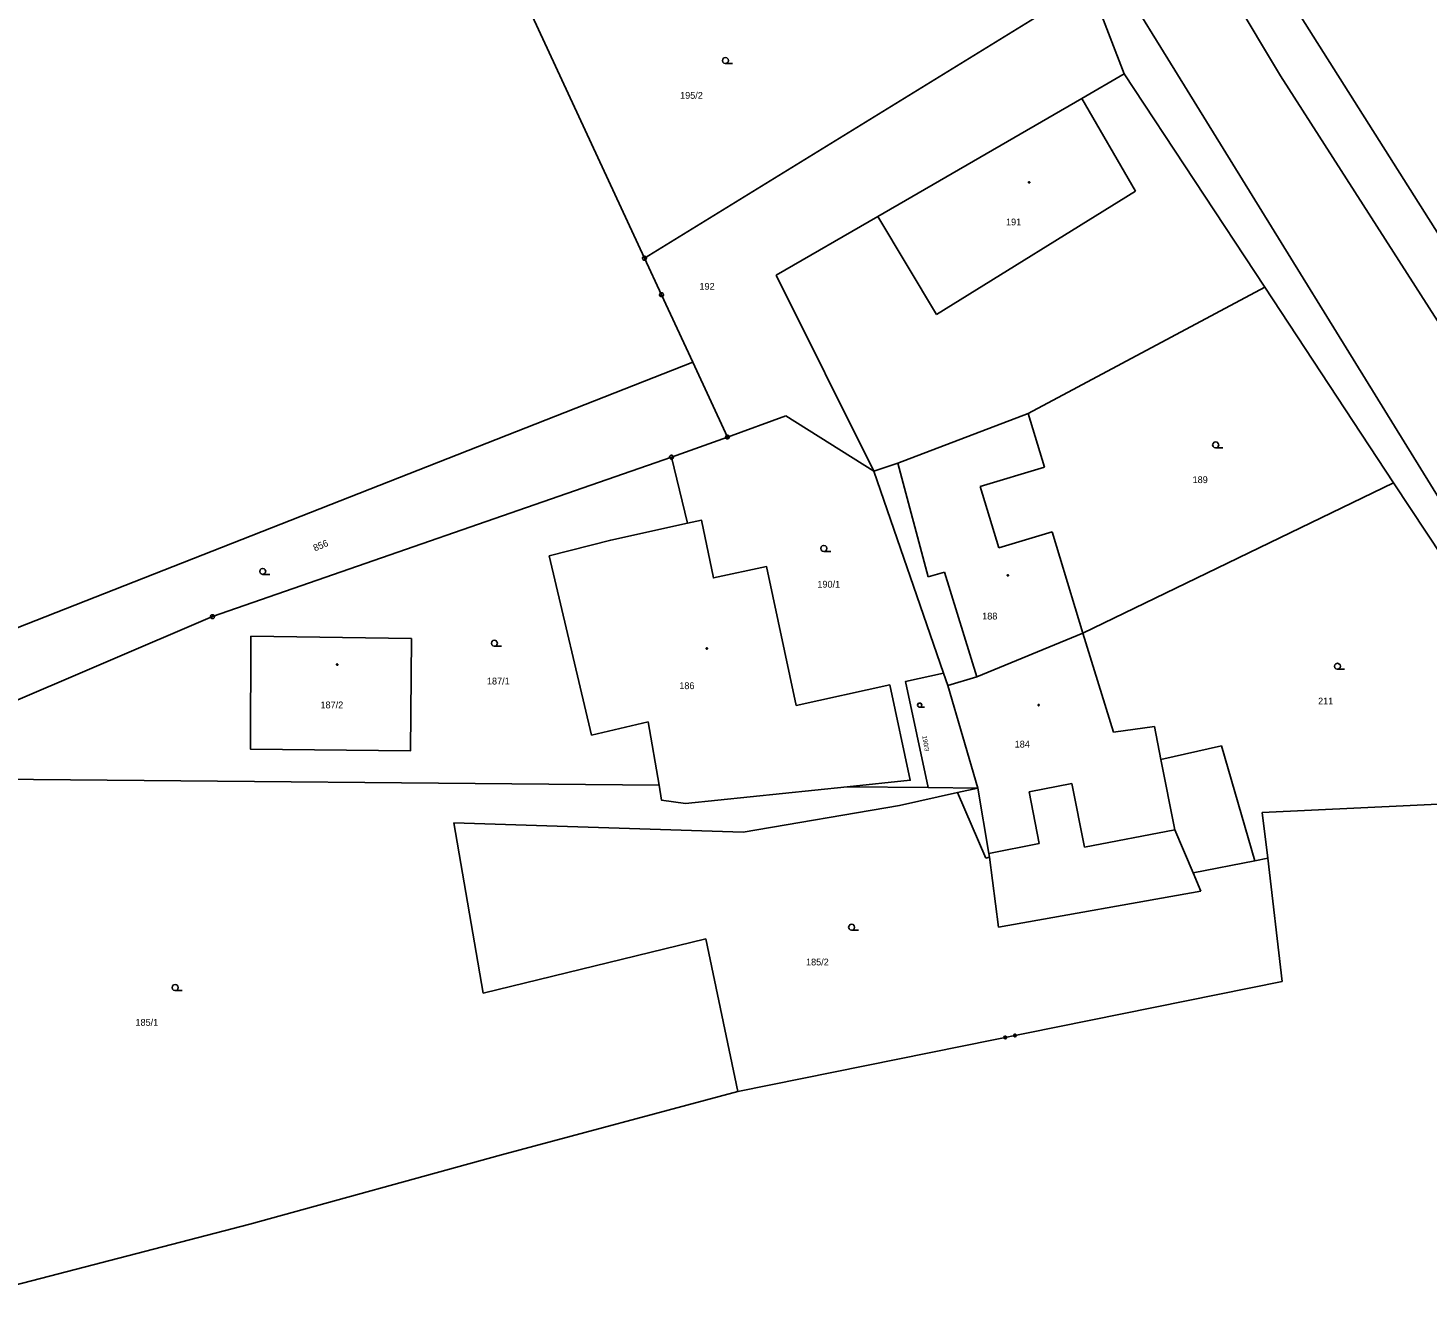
# Model space of a CAD drawing. Extents: x -871430 to -870620, y -1010094 to -1009649.
# Drawn here: x -870992.6 to -870905.1, y -1010094.1 to -1010013.9 of the extents above; entities that cross this region are included whole.
import ezdxf

# ---------------------------------------------------------------- set-up
doc = ezdxf.new("R2010")
doc.units = 0
for name, color, linetype in [('Vrstva 1', 7, 'Continuous'), ('Vrstva 2', 7, 'Continuous'), ('Vrstva 3', 7, 'Continuous'), ('Vrstva 4', 7, 'Continuous'), ('Vrstva 5', 7, 'Continuous'), ('Vrstva 8', 7, 'Continuous')]:
    doc.layers.add(name, color=color, linetype=linetype)

msp = doc.modelspace()

# ---------------------------------------------------------------- linework, layer by layer
at = {"layer": 'Vrstva 1'}
for p, q in [((-870900.92, -1010032.45), (-870917.34, -1010006.41)), ((-870926.27, -1010011.19), (-870954.09, -1010028.31)), ((-870924.1, -1010016.79), (-870926.27, -1010011.19)), ((-870954.09, -1010028.31), (-870961.11, -1010013.17)), ((-870924.1, -1010016.79), (-870926.76, -1010018.33)), ((-870915.32, -1010030.12), (-870924.1, -1010016.79)), ((-870939.51, -1010025.71), (-870926.76, -1010018.33)), ((-870945.85, -1010029.37), (-870939.51, -1010025.71)), ((-870953.03, -1010030.59), (-870954.09, -1010028.31)), ((-870945.85, -1010029.37), (-870939.76, -1010041.62)), ((-870953.03, -1010030.59), (-870951.07, -1010034.81)), ((-870930.1, -1010038.02), (-870915.32, -1010030.12)), ((-870907.27, -1010042.34), (-870915.32, -1010030.12)), ((-871000.46, -1010054.22), (-870951.07, -1010034.81)), ((-870951.07, -1010034.81), (-870948.91, -1010039.48)), ((-870945.25, -1010038.16), (-870948.91, -1010039.48)), ((-870939.76, -1010041.62), (-870945.25, -1010038.16)), ((-870938.26, -1010041.12), (-870930.1, -1010038.02)), ((-870930.1, -1010038.02), (-870929.09, -1010041.37)), ((-870948.91, -1010039.48), (-870952.4, -1010040.74)), ((-870952.4, -1010040.74), (-870981.09, -1010050.7)), ((-870951.39, -1010044.87), (-870952.4, -1010040.74)), ((-870938.26, -1010041.12), (-870939.76, -1010041.62)), ((-870929.09, -1010041.37), (-870933.11, -1010042.58)), ((-870939.76, -1010041.62), (-870935.39, -1010054.23)), ((-870933.11, -1010042.58), (-870931.95, -1010046.41)), ((-870926.69, -1010051.73), (-870907.27, -1010042.34)), ((-870894.37, -1010061.92), (-870907.27, -1010042.34)), ((-870928.61, -1010045.4), (-870931.95, -1010046.41)), ((-870928.61, -1010045.4), (-870926.69, -1010051.73)), ((-870981.09, -1010050.7), (-871004.66, -1010060.76)), ((-870933.31, -1010054.47), (-870926.69, -1010051.73)), ((-870926.69, -1010051.73), (-870924.77, -1010057.92)), ((-870935.39, -1010054.23), (-870935.12, -1010055.01)), ((-870933.31, -1010054.47), (-870935.12, -1010055.01)), ((-870935.12, -1010055.01), (-870933.26, -1010061.41)), ((-870924.77, -1010057.92), (-870922.21, -1010057.57)), ((-870921.82, -1010059.62), (-870922.21, -1010057.57)), ((-870921.82, -1010059.62), (-870918.03, -1010058.77)), ((-870918.03, -1010058.77), (-870915.95, -1010065.95)), ((-871004.66, -1010060.76), (-870953.18, -1010061.23)), ((-870941.43, -1010061.33), (-870936.36, -1010061.38)), ((-870936.36, -1010061.38), (-870933.26, -1010061.41)), ((-870934.53, -1010061.69), (-870933.26, -1010061.41)), ((-870938.15, -1010062.49), (-870934.53, -1010061.69)), ((-870932.75, -1010065.79), (-870934.53, -1010061.69)), ((-870915.49, -1010062.94), (-870894.37, -1010061.92)), ((-870947.92, -1010064.16), (-870938.15, -1010062.49)), ((-870915.13, -1010065.79), (-870915.49, -1010062.94)), ((-870964.17, -1010074.23), (-870966, -1010063.59)), ((-870966, -1010063.59), (-870947.92, -1010064.16)), ((-870932.75, -1010065.79), (-870932.53, -1010065.73)), ((-870932.53, -1010065.73), (-870931.97, -1010070.11)), ((-870915.13, -1010065.79), (-870915.95, -1010065.95)), ((-870914.23, -1010073.5), (-870915.13, -1010065.79)), ((-870915.95, -1010065.95), (-870919.79, -1010066.7)), ((-870919.31, -1010067.86), (-870919.79, -1010066.7)), ((-870931.97, -1010070.11), (-870919.31, -1010067.86)), ((-870950.25, -1010070.83), (-870964.17, -1010074.23)), ((-870948.25, -1010080.36), (-870950.25, -1010070.83)), ((-870948.25, -1010080.36), (-870914.23, -1010073.5)), ((-870963.03, -1010084.32), (-870948.25, -1010080.36)), ((-870978.75, -1010088.66), (-870963.03, -1010084.32)), ((-870999.93, -1010094.14), (-870978.75, -1010088.66))]:
    msp.add_line(p, q, dxfattribs=at)
for points in [[(-870960.05, -1010046.91), (-870956.2, -1010045.92), (-870951.39, -1010044.87)], [(-870951.39, -1010044.87), (-870950.52, -1010044.68), (-870949.78, -1010048.28), (-870946.46, -1010047.57), (-870944.6, -1010056.25), (-870938.76, -1010054.97), (-870937.48, -1010060.92), (-870941.43, -1010061.33)], [(-870953.18, -1010061.23), (-870953.86, -1010057.28), (-870957.39, -1010058.1), (-870960.05, -1010046.91)], [(-870978.7, -1010051.93), (-870968.65, -1010052.07), (-870968.71, -1010059.08), (-870978.71, -1010058.99), (-870978.7, -1010051.93)], [(-870936.36, -1010061.38), (-870937.78, -1010054.76), (-870935.39, -1010054.23)], [(-870953.18, -1010061.23), (-870953.02, -1010062.17), (-870951.53, -1010062.38), (-870941.43, -1010061.33)], [(-870931.518, -1010076.904), (-870931.462, -1010076.942), (-870931.449, -1010077.008), (-870931.486, -1010077.064), (-870931.552, -1010077.077), (-870931.608, -1010077.04), (-870931.621, -1010076.974), (-870931.584, -1010076.918), (-870931.518, -1010076.904), (-870931.519, -1010076.915), (-870931.577, -1010076.927), (-870931.593, -1010076.95), (-870931.495, -1010076.93), (-870931.471, -1010076.946), (-870931.609, -1010076.974), (-870931.605, -1010076.993), (-870931.467, -1010076.966), (-870931.463, -1010076.985), (-870931.601, -1010077.013), (-870931.597, -1010077.033), (-870931.46, -1010077.005), (-870931.475, -1010077.028), (-870931.573, -1010077.048), (-870931.55, -1010077.064), (-870931.491, -1010077.052)], [(-870930.905, -1010076.781), (-870930.849, -1010076.818), (-870930.836, -1010076.884), (-870930.873, -1010076.94), (-870930.939, -1010076.954), (-870930.995, -1010076.916), (-870931.009, -1010076.85), (-870930.972, -1010076.794), (-870930.905, -1010076.781), (-870930.911, -1010076.792), (-870930.97, -1010076.804), (-870930.985, -1010076.828), (-870930.887, -1010076.808), (-870930.864, -1010076.823), (-870931.001, -1010076.851), (-870930.997, -1010076.871), (-870930.86, -1010076.843), (-870930.856, -1010076.863), (-870930.993, -1010076.89), (-870930.989, -1010076.91), (-870930.852, -1010076.882), (-870930.867, -1010076.906), (-870930.965, -1010076.926), (-870930.942, -1010076.941), (-870930.883, -1010076.929)]]:
    msp.add_lwpolyline(points, dxfattribs=at)
at = {"layer": 'Vrstva 3'}
for points in [[(-870949.03, -1010016.15), (-870949.125, -1010016.125), (-870949.192, -1010016.055), (-870949.218, -1010015.962), (-870949.192, -1010015.87), (-870949.125, -1010015.8), (-870949.03, -1010015.775), (-870948.935, -1010015.8), (-870948.868, -1010015.87), (-870948.842, -1010015.962), (-870948.868, -1010016.055), (-870948.935, -1010016.125), (-870949.03, -1010016.15), (-870948.592, -1010016.15)], [(-870918.39, -1010040.16), (-870918.485, -1010040.135), (-870918.552, -1010040.065), (-870918.578, -1010039.972), (-870918.552, -1010039.88), (-870918.485, -1010039.81), (-870918.39, -1010039.785), (-870918.295, -1010039.81), (-870918.228, -1010039.88), (-870918.202, -1010039.972), (-870918.228, -1010040.065), (-870918.295, -1010040.135), (-870918.39, -1010040.16), (-870917.952, -1010040.16)], [(-870942.88, -1010046.63), (-870942.975, -1010046.605), (-870943.042, -1010046.535), (-870943.068, -1010046.442), (-870943.042, -1010046.35), (-870942.975, -1010046.28), (-870942.88, -1010046.255), (-870942.785, -1010046.28), (-870942.718, -1010046.35), (-870942.692, -1010046.442), (-870942.718, -1010046.535), (-870942.785, -1010046.605), (-870942.88, -1010046.63), (-870942.442, -1010046.63)], [(-870977.95, -1010048.06), (-870978.045, -1010048.035), (-870978.112, -1010047.965), (-870978.138, -1010047.872), (-870978.112, -1010047.78), (-870978.045, -1010047.71), (-870977.95, -1010047.685), (-870977.855, -1010047.71), (-870977.788, -1010047.78), (-870977.762, -1010047.872), (-870977.788, -1010047.965), (-870977.855, -1010048.035), (-870977.95, -1010048.06), (-870977.512, -1010048.06)], [(-870963.47, -1010052.55), (-870963.565, -1010052.525), (-870963.632, -1010052.455), (-870963.658, -1010052.362), (-870963.632, -1010052.27), (-870963.565, -1010052.2), (-870963.47, -1010052.175), (-870963.375, -1010052.2), (-870963.308, -1010052.27), (-870963.282, -1010052.362), (-870963.308, -1010052.455), (-870963.375, -1010052.525), (-870963.47, -1010052.55), (-870963.032, -1010052.55)], [(-870910.78, -1010053.99), (-870910.875, -1010053.965), (-870910.942, -1010053.895), (-870910.968, -1010053.802), (-870910.942, -1010053.71), (-870910.875, -1010053.64), (-870910.78, -1010053.615), (-870910.685, -1010053.64), (-870910.618, -1010053.71), (-870910.592, -1010053.802), (-870910.618, -1010053.895), (-870910.685, -1010053.965), (-870910.78, -1010053.99), (-870910.342, -1010053.99)], [(-870936.89, -1010056.35), (-870936.954, -1010056.333), (-870936.999, -1010056.286), (-870937.016, -1010056.224), (-870936.999, -1010056.162), (-870936.954, -1010056.116), (-870936.89, -1010056.099), (-870936.826, -1010056.116), (-870936.781, -1010056.162), (-870936.764, -1010056.224), (-870936.781, -1010056.286), (-870936.826, -1010056.333), (-870936.89, -1010056.35), (-870936.597, -1010056.35)], [(-870941.14, -1010070.29), (-870941.235, -1010070.265), (-870941.302, -1010070.195), (-870941.328, -1010070.102), (-870941.302, -1010070.01), (-870941.235, -1010069.94), (-870941.14, -1010069.915), (-870941.045, -1010069.94), (-870940.978, -1010070.01), (-870940.952, -1010070.102), (-870940.978, -1010070.195), (-870941.045, -1010070.265), (-870941.14, -1010070.29), (-870940.702, -1010070.29)], [(-870983.42, -1010074.06), (-870983.515, -1010074.035), (-870983.582, -1010073.965), (-870983.608, -1010073.872), (-870983.582, -1010073.78), (-870983.515, -1010073.71), (-870983.42, -1010073.685), (-870983.325, -1010073.71), (-870983.258, -1010073.78), (-870983.232, -1010073.872), (-870983.258, -1010073.965), (-870983.325, -1010074.035), (-870983.42, -1010074.06), (-870982.982, -1010074.06)]]:
    msp.add_lwpolyline(points, dxfattribs=at)
at = {"layer": 'Vrstva 4'}
for p, q in [((-870991.3, -1009902.71), (-870921.37, -1010015.86)), ((-870914.33, -1010016.91), (-870955.86, -1009947.84)), ((-870921.37, -1010015.86), (-870879.42, -1010083.87)), ((-870873.64, -1010080.52), (-870914.33, -1010016.91)), ((-870923.41, -1010024.12), (-870926.76, -1010018.33)), ((-870935.84, -1010031.82), (-870923.41, -1010024.12)), ((-870939.51, -1010025.71), (-870935.84, -1010031.82)), ((-870938.26, -1010041.12), (-870936.36, -1010048.21)), ((-870936.36, -1010048.21), (-870935.33, -1010047.93)), ((-870935.33, -1010047.93), (-870933.31, -1010054.47)), ((-870920.95, -1010064.01), (-870921.82, -1010059.62)), ((-870932.56, -1010065.5), (-870933.26, -1010061.41)), ((-870927.38, -1010061.12), (-870930.05, -1010061.65)), ((-870926.59, -1010065.11), (-870927.38, -1010061.12)), ((-870930.05, -1010061.65), (-870929.42, -1010064.88)), ((-870920.95, -1010064.01), (-870926.59, -1010065.11)), ((-870919.79, -1010066.7), (-870920.95, -1010064.01)), ((-870929.42, -1010064.88), (-870932.56, -1010065.5)), ((-870932.56, -1010065.5), (-870932.53, -1010065.73))]:
    msp.add_line(p, q, dxfattribs=at)
at = {"layer": 'Vrstva 5'}
for points in [[(-870930.05, -1010023.528), (-870930.025, -1010023.532), (-870930.013, -1010023.555), (-870930.008, -1010023.57), (-870930.013, -1010023.592), (-870930.033, -1010023.61), (-870930.05, -1010023.612), (-870930.072, -1010023.605), (-870930.088, -1010023.59), (-870930.092, -1010023.57), (-870930.088, -1010023.548), (-870930.068, -1010023.53), (-870930.05, -1010023.528)], [(-870931.38, -1010048.078), (-870931.355, -1010048.082), (-870931.342, -1010048.105), (-870931.338, -1010048.12), (-870931.342, -1010048.142), (-870931.362, -1010048.16), (-870931.38, -1010048.162), (-870931.402, -1010048.155), (-870931.418, -1010048.14), (-870931.422, -1010048.12), (-870931.418, -1010048.098), (-870931.398, -1010048.08), (-870931.38, -1010048.078)], [(-870950.19, -1010052.648), (-870950.165, -1010052.652), (-870950.152, -1010052.675), (-870950.148, -1010052.69), (-870950.152, -1010052.712), (-870950.172, -1010052.73), (-870950.19, -1010052.732), (-870950.212, -1010052.725), (-870950.227, -1010052.71), (-870950.232, -1010052.69), (-870950.227, -1010052.668), (-870950.207, -1010052.65), (-870950.19, -1010052.648)], [(-870973.29, -1010053.658), (-870973.265, -1010053.662), (-870973.253, -1010053.685), (-870973.248, -1010053.7), (-870973.253, -1010053.722), (-870973.273, -1010053.74), (-870973.29, -1010053.742), (-870973.312, -1010053.735), (-870973.328, -1010053.72), (-870973.332, -1010053.7), (-870973.328, -1010053.678), (-870973.308, -1010053.66), (-870973.29, -1010053.658)], [(-870929.45, -1010056.188), (-870929.425, -1010056.192), (-870929.412, -1010056.215), (-870929.408, -1010056.23), (-870929.412, -1010056.252), (-870929.432, -1010056.27), (-870929.45, -1010056.272), (-870929.472, -1010056.265), (-870929.487, -1010056.25), (-870929.492, -1010056.23), (-870929.487, -1010056.208), (-870929.467, -1010056.19), (-870929.45, -1010056.188)]]:
    msp.add_lwpolyline(points, dxfattribs=at)
at = {"layer": 'Vrstva 8'}
for p, q in [((-870954.102, -1010028.31), (-870954.078, -1010028.31)), ((-870953.042, -1010030.59), (-870953.018, -1010030.59)), ((-870948.922, -1010039.48), (-870948.898, -1010039.48)), ((-870952.412, -1010040.74), (-870952.388, -1010040.74)), ((-870981.102, -1010050.7), (-870981.078, -1010050.7))]:
    msp.add_line(p, q, dxfattribs=at)
for points in [[(-870954.052, -1010028.19), (-870953.99, -1010028.238), (-870953.965, -1010028.31), (-870953.99, -1010028.383), (-870954.052, -1010028.43), (-870954.128, -1010028.43), (-870954.19, -1010028.383), (-870954.215, -1010028.31), (-870954.19, -1010028.238), (-870954.128, -1010028.19), (-870954.052, -1010028.19)], [(-870952.992, -1010030.47), (-870952.93, -1010030.518), (-870952.905, -1010030.59), (-870952.93, -1010030.662), (-870952.992, -1010030.71), (-870953.068, -1010030.71), (-870953.13, -1010030.662), (-870953.155, -1010030.59), (-870953.13, -1010030.518), (-870953.068, -1010030.47), (-870952.992, -1010030.47)], [(-870948.872, -1010039.36), (-870948.81, -1010039.408), (-870948.785, -1010039.48), (-870948.81, -1010039.552), (-870948.872, -1010039.6), (-870948.948, -1010039.6), (-870949.01, -1010039.552), (-870949.035, -1010039.48), (-870949.01, -1010039.408), (-870948.948, -1010039.36), (-870948.872, -1010039.36)], [(-870952.362, -1010040.62), (-870952.3, -1010040.668), (-870952.275, -1010040.74), (-870952.3, -1010040.812), (-870952.362, -1010040.86), (-870952.438, -1010040.86), (-870952.5, -1010040.812), (-870952.525, -1010040.74), (-870952.5, -1010040.668), (-870952.438, -1010040.62), (-870952.362, -1010040.62)], [(-870981.052, -1010050.58), (-870980.99, -1010050.628), (-870980.965, -1010050.7), (-870980.99, -1010050.772), (-870981.052, -1010050.82), (-870981.128, -1010050.82), (-870981.19, -1010050.772), (-870981.215, -1010050.7), (-870981.19, -1010050.628), (-870981.128, -1010050.58), (-870981.052, -1010050.58)]]:
    msp.add_lwpolyline(points, dxfattribs=at)

# ---------------------------------------------------------------- texts
at = {"layer": 'Vrstva 2'}
for s, p in [('195/2', (-870951.862, -1010018.35)), ('191', (-870931.492, -1010026.26)), ('192', (-870950.652, -1010030.28)), ('189', (-870919.832, -1010042.36)), ('190/1', (-870943.281, -1010048.89)), ('188', (-870932.982, -1010050.88)), ('187/1', (-870963.935, -1010054.94)), ('186', (-870951.912, -1010055.23)), ('187/2', (-870974.337, -1010056.43)), ('211', (-870911.991, -1010056.19)), ('184', (-870930.952, -1010058.88)), ('185/2', (-870943.992, -1010072.49)), ('185/1', (-870985.902, -1010076.26))]:
    msp.add_text(s, height=0.425, dxfattribs=at).set_placement(p)
for s, height, rotation, p in [('856', 0.425, 22.74643, (-870974.682, -1010046.631)), ('190/3', 0.285, 279.43152, (-870936.726, -1010058.162))]:
    msp.add_text(s, height=height, rotation=rotation, dxfattribs=at).set_placement(p)

doc.saveas('drawing.dxf')
